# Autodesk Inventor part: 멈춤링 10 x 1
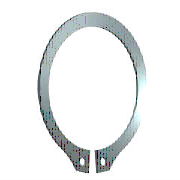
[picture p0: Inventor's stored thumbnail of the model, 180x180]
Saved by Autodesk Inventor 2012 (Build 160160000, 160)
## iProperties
IsCustomPart: 0
Company: 한국ATC센터
Created: 2014-07
Part Number: 멈춤링 10 x 1
Material: Steel, Mild
Description: 리테이닝 링(C형)
Document SubType Name: Modeling
Standard: KS B 1336
Designer: KYOUNG IL JANG
Standards Organization: KS
Language: ko-KR
Size Designation: 10 x 1
Categories: <MemberInstance><Categories><Category DisplayName="샤프트 부품" InternalName="7f7aeb1f-a693-4053-b835-cee3144e0d98" Mnemonic="SHFT"><Category DisplayName="써클립" Inter
Density: 7.86 g/cm^3
Mass: 0.423087 g
Surface Area: 1.9243 cm^2
Volume: 0.0538279 cm^3
Author: KYOUNG IL JANG
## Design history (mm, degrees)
sketch "스케치1"
  geometry: L1 (-6, 0)-(6, 0) reference; L2 (0, 20.189)-(0, -80.536) reference; L3 (-48.09, 0)-(48.09, 0) reference; L4 (-0.3, -9.791)-(-0.3, -12.791); L5 (-0.3, -6.54)-(-0.3, -13.29); L6 (-2.795, 1.6)-(3.672, 1.6); L7 (0.3, -6.54)-(0.3, -13.29); L8 (0.3, -9.791)-(0.3, -12.791); C1 r 0.6 at (-1.2, -11.486); C2 r 0.6 at (1.2, -11.486); A1 r 4.8 centre (0, -5) between (0.3, -9.791) and (-0.3, -9.791); A2 r 6.2 centre (0, -4.6) between (2.988, -10.033) and (-2.988, -10.033); A3 r 7.796 centre (0, -5) between (-1.418, -12.666) and (-0.3, -12.791); A4 r 1.2 centre (-1.2, -11.486) between (-2.383, -11.285) and (-1.418, -12.666); A5 r 1.2 centre (-3.566, -11.084) between (-2.383, -11.285) and (-2.988, -10.033); A6 r 1.2 centre (3.566, -11.084) between (2.988, -10.033) and (2.383, -11.285); A7 r 1.2 centre (1.2, -11.486) between (1.418, -12.666) and (2.383, -11.285); A8 r 7.796 centre (0, -5) between (0.3, -12.791) and (1.418, -12.666)
  constraints: 16 point on circle, 12 end point, 10 centre point, 9 symmetric about line, 5 point on line, 4 tangent, 3 coincident, 2 horizontal, 1 perpendicular, 1 vertical, 5 other
  dimensions: "d0" = 9.6 diameter of A1 (= ND); "d1" = 3 distance of L4.end L4.start (= SRB2); "d6" = 0.3 distance between parallel lines of L2 L5 (= 0.25 x SD5); "d7" = 1.6 distance between parallel lines of L6 L3 (= SRB1); "d8" = 0.4 distance of A1.centre A2.centre (= 0.25 x SRB1); "d9" = 1.2 radius of A4 (= SD5); "d10" = 1.2 radius of A5 (= SD5); "d11" = 0.9 distance from line of L4 A4.centre (= 0.75 x SD5); "d12" = 1.2 diameter of C1 (= SD5); "d13" = 1.2 diameter of C2 (= SD5); "d14" = 5 distance from line of A1.centre L1 (= 0.5 x WD)
extrude "본체" new body sketch "스케치1" distance "d2" = 1 (= SD); taper "d3" = 0 deg
workaxis "Work Axis1"
workplane "Work Plane1"
body "Solid1"
other parameters: "SD" = 1 [user parameter; used in 1 equation term], "SRB1" = 1.6 [user parameter; used in 2 equation terms], "ND" = 9.6 [user parameter; used in 1 equation term], "SRB2" = 3 [user parameter; used in 1 equation term], "SD5" = 1.2 [user parameter; used in 6 equation terms], "d15" = 0, "d16" = 0, "d17" = 0, "d41" = 0, "d42" = 0, "SD3" = 9.3 [user parameter], "WDMAX" = 11 [user parameter]
